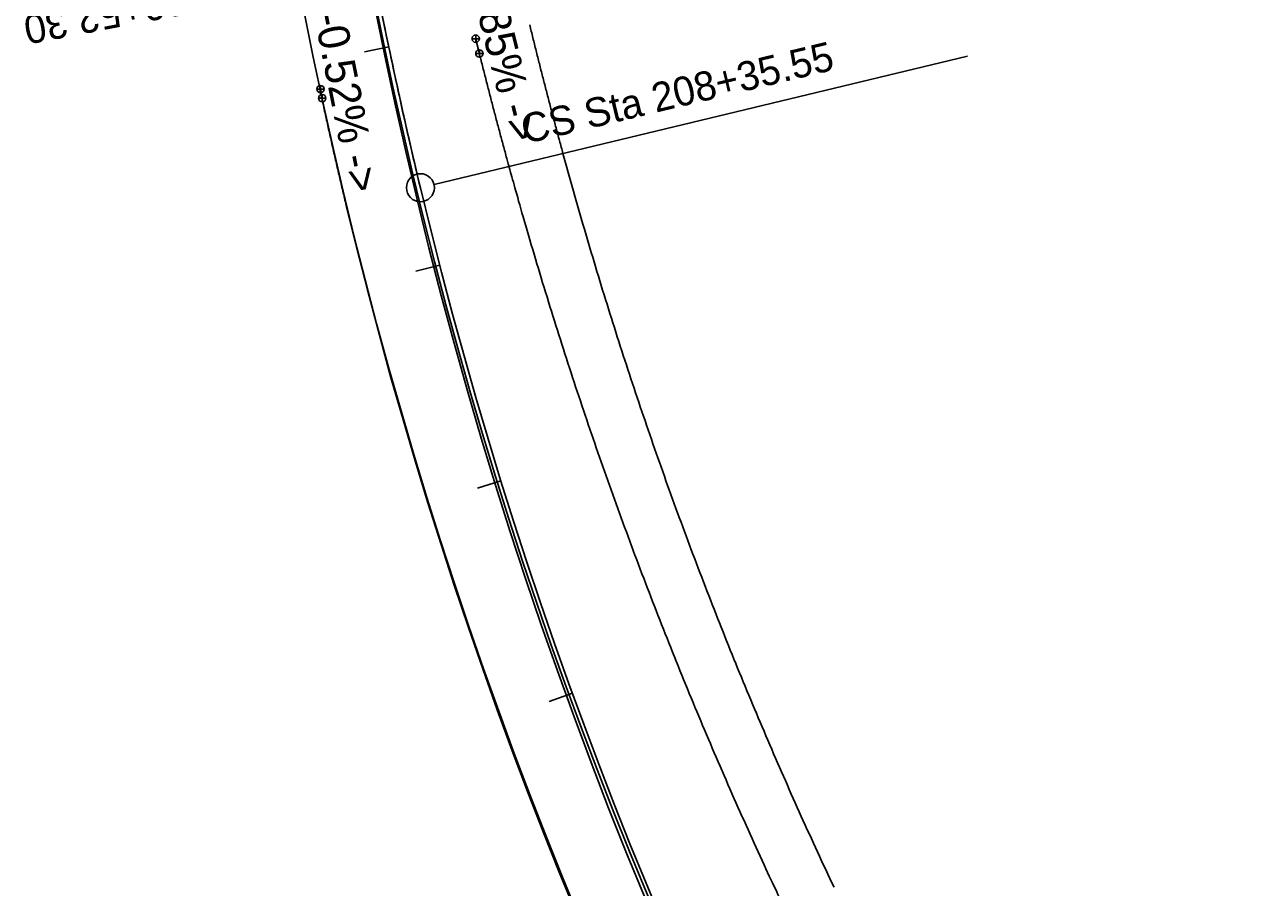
# Model space of a CAD drawing. Extents: x 5180909 to 5237144, y 3695282 to 3720102.
# Drawn here: x 5197771 to 5198322, y 3704056 to 3704440 of the extents above; entities that cross this region are included whole.
import ezdxf

# ---------------------------------------------------------------- set-up
doc = ezdxf.new("R2010")
doc.units = 0
for name, color, linetype in [('Alignment', 7, 'Continuous'), ('Default', 7, 'Continuous'), ('DisFieldPoint', 7, 'Continuous'), ('dsnEntrancePaved', 7, 'Continuous'), ('dsnShadingGranular', 7, 'Continuous'), ('dsnSidewalkShadingRamp', 7, 'Continuous'), ('dsnStgShadingPropGrdLim', 7, 'Continuous')]:
    doc.layers.add(name, color=color, linetype=linetype)

msp = doc.modelspace()

# ---------------------------------------------------------------- linework, layer by layer
at = {"layer": 'Alignment'}
msp.add_arc((5199969.76, 3704853.24), 2080, 193.50367, 260.03022, dxfattribs=at)
msp.add_open_spline([(5197947.26, 3704367.55), (5197944.99, 3704377), (5197940.58, 3704395.94), (5197932.25, 3704433.93), (5197922.68, 3704481.59), (5197912.26, 3704538.98), (5197902.64, 3704596.52), (5197895.08, 3704644.54), (5197889.16, 3704682.98), (5197886.23, 3704702.2), (5197884.76, 3704711.81)], degree=3, dxfattribs=at)
at = {"layer": 'Default'}
msp.add_arc((5199969.76, 3704853.24), 2080, 193.50367, 260.03022, dxfattribs=at)
at = {"layer": 'DisFieldPoint'}
for radius in [2083.48, 2115.48]:
    msp.add_arc((5199970.64, 3704856.44), radius, 191.19211, 260.03431, dxfattribs=at)
at = {"layer": 'dsnEntrancePaved'}
for p, q in [((5197971.93, 3704432.37), (5197971.93, 3704435.65)), ((5197970.29, 3704434.01), (5197973.57, 3704434.01)), ((5197971.93, 3704434.01), (5197973.58, 3704427.4)), ((5197971.94, 3704427.4), (5197975.22, 3704427.4)), ((5197973.58, 3704425.76), (5197973.58, 3704429.04)), ((5197902.67, 3704409.91), (5197902.67, 3704413.19)), ((5197901.03, 3704411.55), (5197904.31, 3704411.55)), ((5197901.83, 3704407.48), (5197905.11, 3704407.48)), ((5197902.67, 3704411.55), (5197903.47, 3704407.48)), ((5197903.47, 3704405.84), (5197903.47, 3704409.12))]:
    msp.add_line(p, q, dxfattribs=at)
for centre in [(5197971.93, 3704434.01), (5197973.58, 3704427.4), (5197902.67, 3704411.55), (5197903.47, 3704407.48)]:
    msp.add_circle(centre, 1.64, dxfattribs=at)
msp.add_arc((5199969.76, 3704853.24), 2080, 193.50367, 260.03022, dxfattribs=at)
msp.add_open_spline([(5197884.76, 3704711.81), (5197886.96, 3704697.39), (5197891.36, 3704668.56), (5197900.32, 3704610.92), (5197912.09, 3704538.96), (5197925.37, 3704467.25), (5197937.34, 3704410.16), (5197943.85, 3704381.73), (5197947.26, 3704367.55)], degree=3, dxfattribs=at)
at = {"layer": 'dsnShadingGranular'}
for p in [(5197986.99, 3704376.31), (5197986.99, 3704376.31), (5197986.99, 3704376.31), (5197987.02, 3704376.19), (5197987.02, 3704376.19), (5197987.02, 3704376.19)]:
    msp.add_line(p, (5197987.02, 3704376.19), dxfattribs=at)
for centre, radius, start, end in [((5199967.62, 3704850.97), 2080, 188.68311, 264.85078), ((5199969.76, 3704853.24), 2114, 193.50367, 260.03022)]:
    msp.add_arc(centre, radius, start, end, dxfattribs=at)
for points in [[(5197971.86, 3704434.25), (5197971.87, 3704434.25), (5197972.1, 3704433.29), (5197972.58, 3704431.36), (5197973.3, 3704428.46), (5197974.03, 3704425.55), (5197974.77, 3704422.64), (5197975.5, 3704419.73), (5197976.24, 3704416.82), (5197976.98, 3704413.92), (5197977.73, 3704411.01), (5197978.48, 3704408.11), (5197979.23, 3704405.21), (5197979.99, 3704402.31), (5197980.75, 3704399.42), (5197981.52, 3704396.52), (5197982.29, 3704393.63), (5197983.06, 3704390.74), (5197983.84, 3704387.85), (5197984.62, 3704384.96), (5197985.41, 3704382.07), (5197986.19, 3704379.19), (5197986.72, 3704377.27), (5197986.99, 3704376.31), (5197986.99, 3704376.31)], [(5197914.2, 3704359.61), (5197913.68, 3704361.77), (5197912.65, 3704366.08), (5197911.13, 3704372.56), (5197909.62, 3704379.04), (5197908.14, 3704385.53), (5197906.67, 3704392.02), (5197905.23, 3704398.5), (5197903.8, 3704405), (5197902.86, 3704409.33), (5197902.39, 3704411.49)], [(5197987.02, 3704376.19), (5197987.02, 3704376.18), (5197988.61, 3704370.51), (5197991.77, 3704359.14), (5197996.71, 3704342.14), (5198001.79, 3704325.17), (5198007.02, 3704308.25), (5198012.39, 3704291.37), (5198017.91, 3704274.55), (5198023.58, 3704257.79), (5198029.38, 3704241.07), (5198035.33, 3704224.42), (5198041.43, 3704207.82), (5198047.67, 3704191.28), (5198054.04, 3704174.8), (5198060.56, 3704158.38), (5198067.22, 3704142.02), (5198074.02, 3704125.73), (5198080.96, 3704109.5), (5198088.04, 3704093.33), (5198095.26, 3704077.24), (5198102.58, 3704061.25), (5198107.58, 3704050.67), (5198110.06, 3704045.4), (5198110.06, 3704045.4)]]:
    msp.add_open_spline(points, degree=3, dxfattribs=at)
at = {"layer": 'dsnSidewalkShadingRamp'}
for p, q in [((5197933.12, 3704430.42), (5197922.36, 3704428.16)), ((5197953.34, 3704369.01), (5198191.36, 3704426.17)), ((5197955.86, 3704333.05), (5197945.21, 3704330.3)), ((5197983.18, 3704236.87), (5197972.68, 3704233.61)), ((5198015.1, 3704142.11), (5198004.76, 3704138.35))]:
    msp.add_line(p, q, dxfattribs=at)
msp.add_circle((5197947.26, 3704367.55), 6.25, dxfattribs=at)
for points in [[(5197971.86, 3704434.25), (5197971.87, 3704434.25), (5197972.1, 3704433.29), (5197972.58, 3704431.36), (5197973.3, 3704428.46), (5197974.03, 3704425.55), (5197974.77, 3704422.64), (5197975.5, 3704419.73), (5197976.24, 3704416.82), (5197976.98, 3704413.92), (5197977.73, 3704411.01), (5197978.48, 3704408.11), (5197979.23, 3704405.21), (5197979.99, 3704402.31), (5197980.75, 3704399.42), (5197981.52, 3704396.52), (5197982.29, 3704393.63), (5197983.06, 3704390.74), (5197983.84, 3704387.85), (5197984.62, 3704384.96), (5197985.41, 3704382.07), (5197986.19, 3704379.19), (5197986.72, 3704377.27), (5197986.99, 3704376.31), (5197986.99, 3704376.31)], [(5197971.86, 3704434.25), (5197971.87, 3704434.25), (5197972.1, 3704433.29), (5197972.58, 3704431.36), (5197973.3, 3704428.46), (5197974.03, 3704425.55), (5197974.77, 3704422.64), (5197975.5, 3704419.73), (5197976.24, 3704416.82), (5197976.98, 3704413.92), (5197977.73, 3704411.01), (5197978.48, 3704408.11), (5197979.23, 3704405.21), (5197979.99, 3704402.31), (5197980.75, 3704399.42), (5197981.52, 3704396.52), (5197982.29, 3704393.63), (5197983.06, 3704390.74), (5197983.84, 3704387.85), (5197984.62, 3704384.96), (5197985.41, 3704382.07), (5197986.19, 3704379.19), (5197986.72, 3704377.27), (5197986.99, 3704376.31), (5197986.99, 3704376.31)], [(5197987.02, 3704376.19), (5197987.02, 3704376.18), (5197988.61, 3704370.51), (5197991.77, 3704359.14), (5197996.71, 3704342.14), (5198001.79, 3704325.17), (5198007.02, 3704308.25), (5198012.39, 3704291.37), (5198017.91, 3704274.55), (5198023.58, 3704257.79), (5198029.38, 3704241.07), (5198035.33, 3704224.42), (5198041.43, 3704207.82), (5198047.67, 3704191.28), (5198054.04, 3704174.8), (5198060.56, 3704158.38), (5198067.22, 3704142.02), (5198074.02, 3704125.73), (5198080.96, 3704109.5), (5198088.04, 3704093.33), (5198095.26, 3704077.24), (5198102.58, 3704061.25), (5198107.58, 3704050.67), (5198110.06, 3704045.4), (5198110.06, 3704045.4)], [(5197987.02, 3704376.19), (5197987.02, 3704376.18), (5197988.61, 3704370.51), (5197991.77, 3704359.14), (5197996.71, 3704342.14), (5198001.79, 3704325.17), (5198007.02, 3704308.25), (5198012.39, 3704291.37), (5198017.91, 3704274.55), (5198023.58, 3704257.79), (5198029.38, 3704241.07), (5198035.33, 3704224.42), (5198041.43, 3704207.82), (5198047.67, 3704191.28), (5198054.04, 3704174.8), (5198060.56, 3704158.38), (5198067.22, 3704142.02), (5198074.02, 3704125.73), (5198080.96, 3704109.5), (5198088.04, 3704093.33), (5198095.26, 3704077.24), (5198102.58, 3704061.25), (5198107.58, 3704050.67), (5198110.06, 3704045.4), (5198110.06, 3704045.4)]]:
    msp.add_open_spline(points, degree=3, dxfattribs=at)
at = {"layer": 'dsnStgShadingPropGrdLim'}
for points in [[(5197947.26, 3704367.55), (5197943.85, 3704381.73), (5197937.34, 3704410.16), (5197925.37, 3704467.25), (5197912.09, 3704538.96), (5197900.32, 3704610.92), (5197891.36, 3704668.56), (5197886.96, 3704697.39), (5197884.76, 3704711.81)], [(5197996.04, 3704440.19), (5197996.28, 3704439.23), (5197996.75, 3704437.3), (5197997.46, 3704434.42), (5197998.17, 3704431.53), (5197998.89, 3704428.65), (5197999.61, 3704425.78), (5198000.34, 3704422.9), (5198001.07, 3704420.02), (5198001.8, 3704417.15), (5198002.54, 3704414.28), (5198003.28, 3704411.41), (5198004.02, 3704408.54), (5198004.77, 3704405.68), (5198005.52, 3704402.81), (5198006.27, 3704399.95), (5198007.03, 3704397.09), (5198007.79, 3704394.23), (5198008.56, 3704391.38), (5198009.33, 3704388.52), (5198010.1, 3704385.67), (5198010.62, 3704383.77), (5198010.88, 3704382.82)], [(5198010.88, 3704382.82), (5198012.43, 3704377.2), (5198015.54, 3704365.94), (5198020.39, 3704349.12), (5198025.37, 3704332.34), (5198030.5, 3704315.61), (5198035.77, 3704298.93), (5198041.19, 3704282.3), (5198046.75, 3704265.73), (5198052.45, 3704249.2), (5198058.29, 3704232.74), (5198064.28, 3704216.32), (5198070.41, 3704199.97), (5198076.67, 3704183.67), (5198083.08, 3704167.43), (5198089.62, 3704151.26), (5198096.31, 3704135.14), (5198103.13, 3704119.09), (5198110.09, 3704103.1), (5198117.19, 3704087.18), (5198124.41, 3704071.32), (5198129.34, 3704060.8), (5198131.81, 3704055.55)]]:
    msp.add_open_spline(points, degree=3, dxfattribs=at)

# ---------------------------------------------------------------- texts
at = {"layer": 'dsnEntrancePaved'}
for s, rotation, p in [('Slope=-0.85% ->', 284.0365, (5197953.21, 3704523.31)), ('Slope=-0.52% ->', 281.1489, (5197888.35, 3704502.33))]:
    msp.add_text(s, height=14, rotation=rotation, dxfattribs=at).set_placement(p)
at = {"layer": 'dsnSidewalkShadingRamp'}
for s, rotation, p in [('PI Sta 209+52.30', 190.8241, (5197901.86, 3704469.45)), ('CS Sta 208+35.55', 13.5037, (5197994.01, 3704387))]:
    msp.add_text(s, height=13, rotation=rotation, dxfattribs=at).set_placement(p)

doc.saveas('drawing.dxf')
